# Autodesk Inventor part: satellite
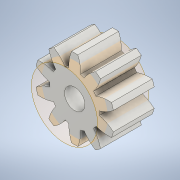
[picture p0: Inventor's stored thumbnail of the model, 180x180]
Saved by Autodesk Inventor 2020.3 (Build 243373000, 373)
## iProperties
CustomPartVersion: 1
Created: 2020-11
Part Number: satellite
Material: Steel
Document SubType Name: Modeling
Designer: ficho
Categories: <?xml version="1.0" encoding="UTF-16"?> <MemberInstance><Categories><FamilyTemplate><FamilyTemplateParameter ValueType="xs:double" Id="1" ObjectReferenceKey="da
Density: 7.85 g/cm^3
Appearance: Steel
Mass: 0.944444 g
Surface Area: 2.49326 cm^2
Volume: 0.120311 cm^3
Author: ficho
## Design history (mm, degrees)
sketch "Sketch1"
  geometry: C1 r 3.9 at (0, 0)
  constraints: 1 centre point
  dimensions: "d0" = 7.8 diameter of C1 (= da_da)
extrude "Extrusion1" new body sketch "Sketch1" distance "d1" = 5 (= da_b); taper "d2" = 0 deg
workplane "Work Plane2"
sketch "Sketch2"
  geometry: C1 r 3.9 at (0, 0) reference; C2 r 3.25 at (0, 0)
  constraints: 1 centre point, 1 coincident
  dimensions: "d3" = 6.5 diameter of C2 (= da_dw)
feature "Diamètre primitif" sketch "Sketch2" dims "d4" = 10, "d5" = 0
workplane "Work Plane8"
workplane "Work Plane9"
feature "Engrenage cylindrique" dims "d4" = 10, "da_b" = 5, "da_d" = 6.5, "da_aw" = 6.5, "da_da" = 7.8, "da_df" = 4.875, "da_dw" = 6.5, angle "da_beta" = 0 deg, "da_lefttooth" = 0, "da_righttooth" = 0
sketch "Esquisse3"
  geometry: 1 further point
hole "Perçage1" sketch "Esquisse3" at (0, 0) diameter "d49" = 2; stored, may be unused: countersink angle "d53" = 90 deg, drill point angle "d55" = 118 deg; dims "d50" = 6, "d51" = 4, "d52" = 2, "d54" = 8
sketch "Esquisse4"
  geometry: L1 (-5.78, 4.885)-(6.372, 4.885); L2 (6.372, 4.885)-(6.372, -4.944); L3 (6.372, -4.944)-(-5.78, -4.944); L4 (-5.78, -4.944)-(-5.78, 4.885); 1 further point
  constraints: 8 end point, 2 parallel, 1 horizontal, 1 perpendicular
extrude "Extrusion2" cut sketch "Esquisse4" distance "d56" = 1; taper "d57" = 0 deg
body "Solid1"
body "Srf1"
other parameters: "d16" = 6.5 (= da_aw), "d17" = 0, "d34" = 18 deg (computed from da_z), "d39" = 0, "d41" = 0, "d43" = 6.5 (= da_aw), "d46" = 6.5 (= da_aw), "d47" = 0, "d48" = 0
